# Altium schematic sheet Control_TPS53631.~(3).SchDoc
size 431 x 279 mm; Date: Not shown in title block; ApprovedBy: Not shown in title block; CheckedBy: Not shown in title block; Author: Not shown in title block; CompanyName: Not shown in title block; Engineer: Not shown in title block; Organization: Not shown in title block; Address1: Not shown in title block; Address2: Not shown in title block; Address3: Not shown in title block; Address4: Not shown in title block; DocumentNumber: 3; Revision: Use project parameter SCH_Rev; SheetNumber: 3; SheetTotal: 5; PageSetup: Record=PageOptions|CenterHorizontal=True|CenterVertical=True|PrintScale=1.00|XCorrection=1.00|YCorrection=1.00|PrintKind=0|BorderSize=5000000|LeftOffset=0|BottomOffset=0|Orientation=2|PaperLength=1000|PaperWidth=1000|Scale=100|PaperSource=15|PrintQuality=600|MediaType=1|DitherType=10|PaperKind=Letter|PrintScaleMode=1
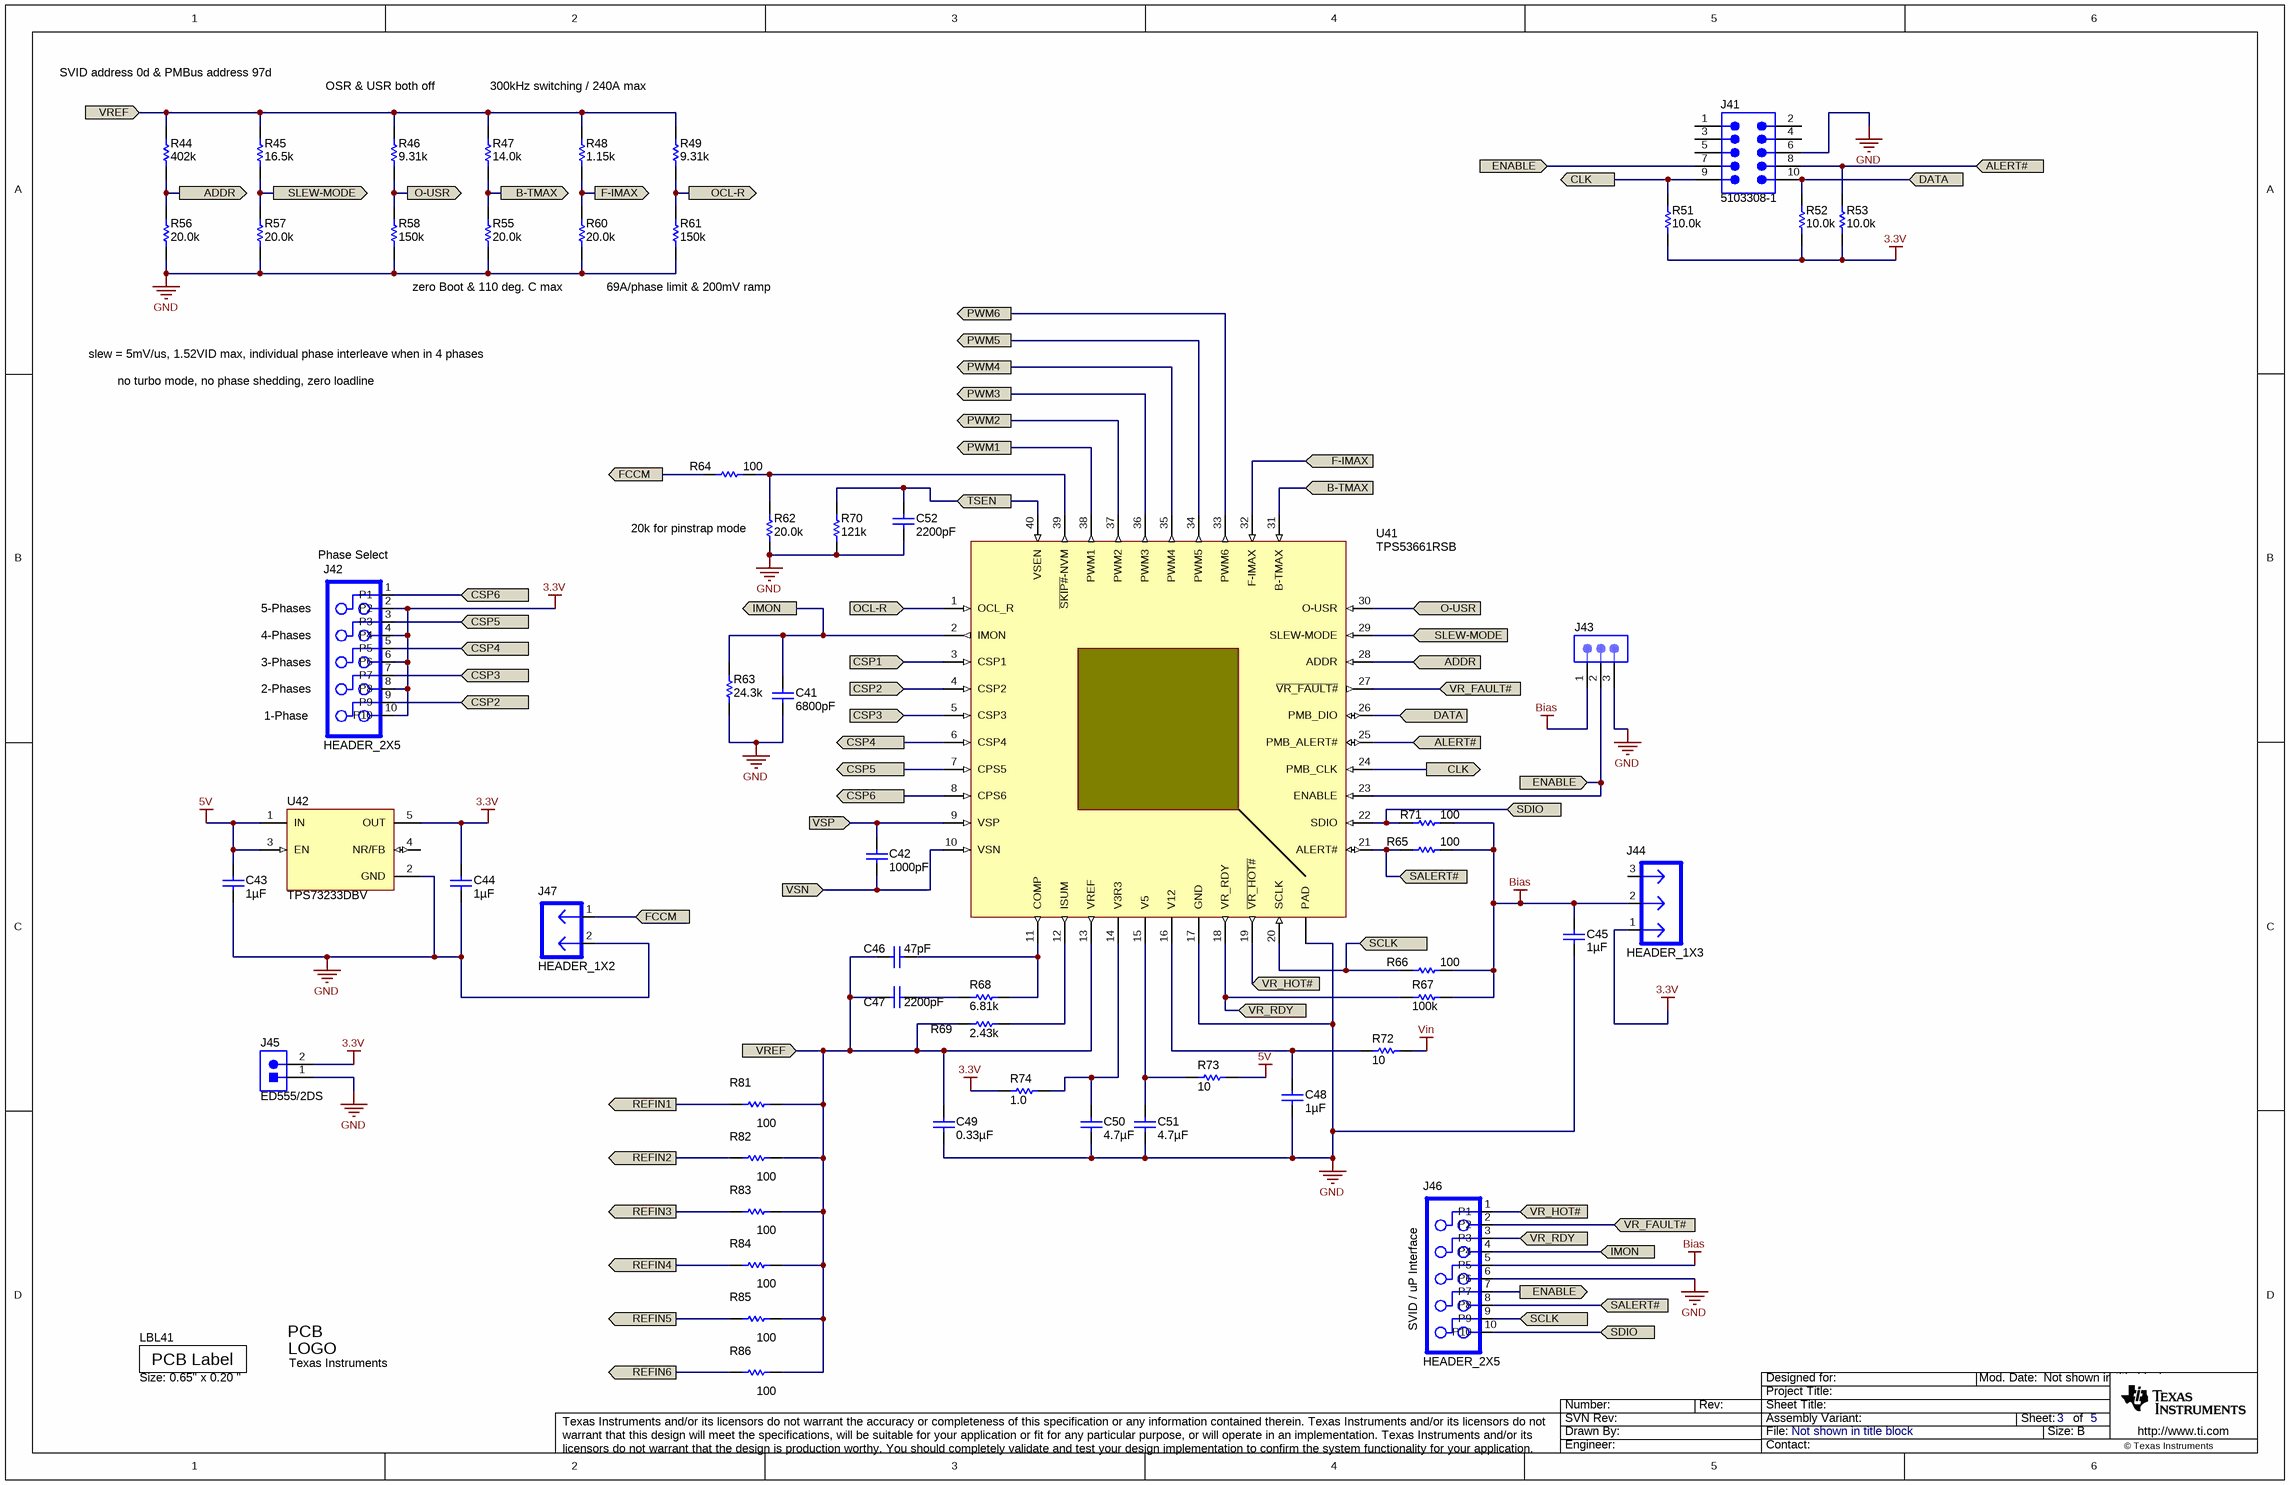
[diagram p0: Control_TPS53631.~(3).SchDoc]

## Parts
C41  ValueDisplayed: 6800pF  [0603]  (hidden comment: 06031C682KAT2A)
C42  ValueDisplayed: 1000pF  [0402]  (hidden comment: C1005X7R1H102K)
C43  ValueDisplayed: 1µF  [0603]  (hidden comment: C1608X5R1E105K080AC)
C44  ValueDisplayed: 1µF  [0603]  (hidden comment: C1608X5R1E105K080AC)
C45  ValueDisplayed: 1µF  [0603]  (hidden comment: C1608X5R1E105K080AC)
C46  ValueDisplayed: 47pF  [0402]  (hidden comment: GRM1555C1H470JA01D)
C47  ValueDisplayed: 2200pF  [0603]  (hidden comment: GRM188R71H222KA01D)
C48  ValueDisplayed: 1µF  [0603]  (hidden comment: C1608X5R1E105K080AC)
C49  ValueDisplayed: 0.33µF  [0402]  (hidden comment: GRM155R60J334KE01D)
C50  ValueDisplayed: 4.7µF  [0402]  (hidden comment: GRM155R61A475M)
C51  ValueDisplayed: 4.7µF  [0402]  (hidden comment: GRM155R61A475M)
C52  ValueDisplayed: 2200pF  [0402]  (hidden comment: C1005X7R1H222K)
J41  5103308-1  [CONN_5103308-1]
J42  HEADER_2X5  [HEADER_2X5]
J43  PBC03SAAN  [PBC03SAAN]  (value not drawn)
J44  HEADER_1X3  [HDR100_1X3]
J45  ED555/2DS  [TERM_BLK_ED555-2DS]
J46  HEADER_2X5  [HEADER_2X5]
J47  HEADER_1X2  [HDR100_1X2]
LBL41  Size: 0.65" x 0.20 "  [Label_650x200]
Logo41  Texas Instruments  [TI_Stacked_Overlay_Medium]  (no BOM)
R44  value 402k  [0402]  (hidden comment: CRCW0402402KFKED)
R45  value 16.5k  [0402]  (hidden comment: CRCW040216K5FKED)
R46  value 9.31k  [0402]  (hidden comment: CRCW04029K31FKED)
R47  value 14.0k  [0402]  (hidden comment: CRCW040214K0FKED)
R48  value 1.15k  [0402]  (hidden comment: CRCW04021K15FKED)
R49  value 9.31k  [0402]  (hidden comment: CRCW04029K31FKED)
R51  value 10.0k  [0402]  (hidden comment: CRCW040210K0FKED)
R52  value 10.0k  [0402]  (hidden comment: CRCW040210K0FKED)
R53  value 10.0k  [0402]  (hidden comment: CRCW040210K0FKED)
R55  value 20.0k  [0402]  (hidden comment: CRCW040220K0FKED)
R56  value 20.0k  [0402]  (hidden comment: CRCW040220K0FKED)
R57  value 20.0k  [0402]  (hidden comment: CRCW040220K0FKED)
R58  value 150k  [0402]  (hidden comment: CRCW0402150KFKED)
R60  value 20.0k  [0402]  (hidden comment: CRCW040220K0FKED)
R61  value 150k  [0402]  (hidden comment: CRCW0402150KFKED)
R62  value 20.0k  [0402]  (hidden comment: CRCW040220K0FKED)
R63  value 24.3k  [0402]  (hidden comment: CRCW040224K3FKED)
R64  value 100  [0402]  (hidden comment: CRCW0402100RJNED)
R65  value 100  [0402]  (hidden comment: CRCW0402100RJNED)
R66  value 100  [0402]  (hidden comment: CRCW0402100RJNED)
R67  value 100k  [0402]  (hidden comment: CRCW0402100KFKED)
R68  value 6.81k  [0402]  (hidden comment: CRCW04026K81FKED)
R69  value 2.43k  [0402]  (hidden comment: CRCW04022K43FKED)
R70  value 121k  [0402]  (hidden comment: CRCW0402121KFKED)
R71  value 100  [0402]  (hidden comment: CRCW0402100RJNED)
R72  value 10  [0402]  (hidden comment: CRCW040210R0JNED)
R73  value 10  [0402]  (hidden comment: CRCW040210R0JNED)
R74  value 1.0  [0402]  (hidden comment: CRCW04021R00JNED)
R81  value 100  [0402]  (hidden comment: CRCW0402100RJNED)
R82  value 100  [0402]  (hidden comment: CRCW0402100RJNED)
R83  value 100  [0402]  (hidden comment: CRCW0402100RJNED)
R84  value 100  [0402]  (hidden comment: CRCW0402100RJNED)
R85  value 100  [0402]  (hidden comment: CRCW0402100RJNED)
R86  value 100  [0402]  (hidden comment: CRCW0402100RJNED)
U41  TPS53661RSB  [RSB0040E]
U42  TPS73233DBV  [DBV0005A_N]

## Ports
ADDR (in), ADDR (out), ALERT#, ALERT# (in), B-TMAX (in), B-TMAX (out), CLK, CSP1 (in), CSP2, CSP2 (in), CSP3, CSP3 (in), CSP4, CSP5, CSP6, DATA, DATA (in), ENABLE, F-IMAX (in), F-IMAX (out), FCCM, IMON, O-USR (in), O-USR (out), OCL-R (in), OCL-R (out), PWM1 (out), PWM2 (out), PWM3 (out), PWM4 (out), PWM5 (out), PWM6 (out), REFIN1 (out), REFIN2 (out), REFIN3 (out), REFIN4 (out), REFIN5 (out), REFIN6 (out), SALERT#, SCLK, SDIO, SLEW-MODE (in), SLEW-MODE (out), TSEN, VR_FAULT#, VR_HOT#, VR_RDY, VREF, VSN (in), VSP (in)

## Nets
3.3V: C44.2 J42.2(P2) J42.4(P4) J42.6(P6) J42.8(P8) J42.10(P10) J44.1 J45.2 R51.2 R52.2 R53.2 R74.1 U42.5(OUT)
5V: C43.2 R73.2 U42.1(IN) U42.3(EN)
Bias: C45.1 J43.1 J44.2 J46.5(P5) R65.1 R66.1 R67.1 R71.1
GND: C41.2 C43.1 C44.1 C45.2 C48.2 C49.2 C50.2 C51.2 C52.2 J41.6 J43.3 J45.1 J46.6(P6) J47.2 R55.1 R56.1 R57.1 R58.1 R60.1 R61.1 R62.1 R63.1 R70.1 U41.17(GND) U41.41(PAD) U42.2(GND)
Vin: R72.2
ADDR: R44.1 R56.2 U41.28(ADDR) ; port ADDR
ALERT#: J41.8 R53.1 U41.25(PMB_ALERT#) ; port ALERT#
B-TMAX: R47.1 R55.2 U41.31(B-TMAX) ; port B-TMAX
CLK: J41.9 R51.1 U41.24(PMB_CLK) ; port CLK
CSP1: U41.3(CSP1) ; port CSP1
CSP2: J42.9(P9) U41.4(CSP2) ; port CSP2
CSP3: J42.7(P7) U41.5(CSP3) ; port CSP3
CSP4: J42.5(P5) U41.6(CSP4) ; port CSP4
CSP5: J42.3(P3) U41.7(CPS5) ; port CSP5
CSP6: J42.1(P1) U41.8(CPS6) ; port CSP6
DATA: J41.10 R52.1 U41.26(PMB_DIO) ; port DATA
ENABLE: J41.7 J43.2 J46.7(P7) U41.23(ENABLE) ; port ENABLE
F-IMAX: R48.1 R60.2 U41.32(F-IMAX) ; port F-IMAX
FCCM: J47.1 R64.2 ; port FCCM
IMON: C41.1 J46.4(P4) R63.2 U41.2(IMON) ; port IMON
O-USR: R46.1 R58.2 U41.30(O-USR) ; port O-USR
OCL-R: R49.1 R61.2 U41.1(OCL_R) ; port OCL-R
PWM1: U41.38(PWM1) ; port PWM1
PWM2: U41.37(PWM2) ; port PWM2
PWM3: U41.36(PWM3) ; port PWM3
PWM4: U41.35(PWM4) ; port PWM4
PWM5: U41.34(PWM5) ; port PWM5
PWM6: U41.33(PWM6) ; port PWM6
REFIN1: R81.2 ; port REFIN1
REFIN2: R82.2 ; port REFIN2
REFIN3: R83.2 ; port REFIN3
REFIN4: R84.2 ; port REFIN4
REFIN5: R85.2 ; port REFIN5
REFIN6: R86.2 ; port REFIN6
SALERT#: J46.8(P8) R65.2 U41.21(ALERT#) ; port SALERT#
SCLK: J46.9(P9) R66.2 U41.20(SCLK) ; port SCLK
SDIO: J46.10(P10) R71.2 U41.22(SDIO) ; port SDIO
SLEW-MODE: R45.1 R57.2 U41.29(SLEW-MODE) ; port SLEW-MODE
TSEN: C52.1 R70.2 U41.40(VSEN) ; port TSEN
VR_FAULT#: J46.2(P2) U41.27(~{VR_FAULT#}) ; port VR_FAULT#
VR_HOT#: J46.1(P1) U41.19(~{VR_HOT#}) ; port VR_HOT#
VR_RDY: J46.3(P3) R67.2 U41.18(VR_RDY) ; port VR_RDY
VREF: C46.1 C47.1 C49.1 R44.2 R45.2 R46.2 R47.2 R48.2 R49.2 R69.1 R81.1 R82.1 R83.1 R84.1 R85.1 R86.1 U41.13(VREF) ; port VREF
VSN: C42.2 U41.10(VSN) ; port VSN
VSP: C42.1 U41.9(VSP) ; port VSP
NetC46_2: C46.2 R68.1 U41.11(COMP)
NetC47_2: C47.2 R68.2
NetC48_1: C48.1 R72.1 U41.16(V12)
NetC50_1: C50.1 R74.2 U41.14(V3R3)
NetC51_1: C51.1 R73.1 U41.15(V5)
NetR62_2: R62.2 R64.1 U41.39(~{SKIP#}-NVM)
NetR69_2: R69.2 U41.12(ISUM)

Not connected (* = marked no-connect by the designer): J41 1 2 3 4 5; J44 3; U42 4(NR/FB)

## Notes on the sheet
- SVID address 0d & PMBus address 97d
- OSR & USR both off
- 300kHz switching / 240A max
- zero Boot & 110 deg. C max
- 69A/phase limit & 200mV ramp
- slew = 5mV/us, 1.52VID max, individual phase interleave when in 4 phases
- no turbo mode, no phase shedding, zero loadline
- (near J42) Phase Select
- (near R62) 20k for pinstrap mode
- 4-Phases
- 5-Phases
- 3-Phases
- 2-Phases
- 1-Phase
- SVID / uP Interface

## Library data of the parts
C41 = 06031C682KAT2A: CAP, CERM, 6800pF, 100V, +/-10%, X7R, 0603; Manufacturer: AVX; Polarized: N; CompType: Capacitor; U/M: EA; Cap_F: 0.0000000068; Tolerance_%: 10; ESR_Ohm: 0.115; Value1: 0.115 ohm; VDC_V: 100; TaMin_C: -55; TaMax_C: 125
C42 = C1005X7R1H102K: CAP, CERM, 1000pF, 50V, +/-10%, X7R, 0402; Manufacturer: TDK; Polarized: N; CompType: Capacitor; U/M: EA; Cap_F: 0.000000001; Tolerance_%: 10; ESR_Ohm: 0.2381; Value1: 0.2381 ohm; VDC_V: 50; TaMin_C: -55; TaMax_C: 125
C43-C45 C48 = C1608X5R1E105K080AC: CAP, CERM, 1uF, 25V, +/-10%, X5R, 0603; Manufacturer: TDK; Polarized: N; CompType: Capacitor; U/M: EA; Cap_F: 0.000001; Tolerance_%: 10; Value1: Unknown; VDC_V: 25; TaMin_C: -55; TaMax_C: 85
C46 = GRM1555C1H470JA01D: CAP, CERM, 47pF, 50V, +/-5%, C0G/NP0, 0402; Manufacturer: MuRata; Polarized: N; CompType: Capacitor; U/M: EA; Cap_F: 0.000000000047; Tolerance_%: 5; Value1: Unknown; VDC_V: 50; TaMin_C: -55; TaMax_C: 125
C47 = GRM188R71H222KA01D: CAP, CERM, 2200pF, 50V, +/-10%, X7R, 0603; Manufacturer: MuRata; Polarized: N; CompType: Capacitor; U/M: EA; Cap_F: 0.0000000022; Tolerance_%: 10; Value1: Unknown; VDC_V: 50; TaMin_C: -55; TaMax_C: 125
C49 = GRM155R60J334KE01D: CAP, CERM, 0.33uF, 6.3V, +/-10%, X5R, 0402; Manufacturer: MuRata; Polarized: N; CompType: Capacitor; U/M: EA; Cap_F: 0.00000033; Tolerance_%: 10; Value1: Unknown; VDC_V: 6.3; TaMin_C: -55; TaMax_C: 85
C50 C51 = GRM155R61A475M: CAP, CERM, 4.7uF, 10V, +/-20%, X5R, 0402; Manufacturer: MuRata; Polarized: N; CompType: Capacitor; U/M: EA; Cap_F: 0.0000047; Tolerance_%: 20; Value1: Unknown; VDC_V: 10; TaMin_C: -55; TaMax_C: 85
C52 = C1005X7R1H222K: CAP, CERM, 2200pF, 50V, +/-10%, X7R, 0402; Manufacturer: TDK; Polarized: N; CompType: Capacitor; U/M: EA; Cap_F: 0.0000000022; Tolerance_%: 10; ESR_Ohm: 0.1433; Value1: 0.1433 ohm; VDC_V: 50; TaMin_C: -55; TaMax_C: 125
J41 = 5103308-1: Header (shrouded), 100mil, 5x2, Gold, TH; Manufacturer: TE Connectivity; SymbolCreator: a0412235; CompType: Connector; U/M: EA
J42 J46 = HEADER_2X5: Header, Male 2x5-pin, 100mil spacing; Manufacturer: Sullins; PartNumber: PEC05DAAN; area: 100000; Value: PEC05DAAN
J43 = PBC03SAAN: Header, TH, 100mil, 1x3, Gold plated, 230 mil above insulator; Manufacturer: Sullins Connector Solutions; U/M: EA
J44 = HEADER_1X3: Header, Male 3-pin, 100mil spacing,; Manufacturer: Sullins; PartNumber: PEC03SAAN; area: 30000; Value: PEC03SAAN
J45 = ED555/2DS: Terminal Block, 6A, 3.5mm Pitch, 2-Pos, TH; Manufacturer: On-Shore Technology; SymbolCreator: a0412235; CompType: Connector; U/M: EA
J47 = HEADER_1X2: Header, Male 2-pin, 100mil spacing,; Manufacturer: Sullins; PartNumber: PEC02SAAN; area: 20000; Value: PEC02SAAN
LBL41 = THT-14-423-10: Thermal Transfer Printable Labels, 0.650" W x 0.200" H - 10,000 per roll; Manufacturer: Brady; SymbolCreator: a0412235; CompType: Label
Logo41 = TI_Logo: Texas Instrument Corporate Signature; SymbolCreator: a0412235
R44 = CRCW0402402KFKED: RES, 402k ohm, 1%, 0.063W, 0402; Manufacturer: Vishay-Dale; CompType: Resistor; Res_ohm: 402000; Tolerance_%: 1; Power_W: 0.063; VDC_V: 50; TempCo: 100 ppm/C; EIA_Code: E96; U/M: EA
R45 = CRCW040216K5FKED: RES, 16.5k ohm, 1%, 0.063W, 0402; Manufacturer: Vishay-Dale; CompType: Resistor; Res_ohm: 16500; Value_Code: 16k5; Tolerance_%: 1; Power_W: 0.063; VDC_V: 50; TempCo: 100 ppm/C; EIA_Code: E96; U/M: EA
R46 R49 = CRCW04029K31FKED: RES, 9.31k ohm, 1%, 0.063W, 0402; Manufacturer: Vishay-Dale; CompType: Resistor; Res_ohm: 9310; Value_Code: 9k31; Tolerance_%: 1; Power_W: 0.063; VDC_V: 50; TempCo: 100 ppm/C; EIA_Code: E96; U/M: EA
R47 = CRCW040214K0FKED: RES, 14.0k ohm, 1%, 0.063W, 0402; Manufacturer: Vishay-Dale; CompType: Resistor; Res_ohm: 14000; Value_Code: 14k0; Tolerance_%: 1; Power_W: 0.063; VDC_V: 50; TempCo: 100 ppm/C; EIA_Code: E96; U/M: EA
R48 = CRCW04021K15FKED: RES, 1.15k ohm, 1%, 0.063W, 0402; Manufacturer: Vishay-Dale; CompType: Resistor; Res_ohm: 1150; Value_Code: 1k15; Tolerance_%: 1; Power_W: 0.063; VDC_V: 50; TempCo: 100 ppm/C; EIA_Code: E96; U/M: EA
R51-R53 = CRCW040210K0FKED: RES, 10.0k ohm, 1%, 0.063W, 0402; Manufacturer: Vishay-Dale; CompType: Resistor; Res_ohm: 10000; Value_Code: 10k0; Tolerance_%: 1; Power_W: 0.063; VDC_V: 50; TempCo: 100 ppm/C; EIA_Code: E96; U/M: EA
R55-R57 R60 R62 = CRCW040220K0FKED: RES, 20.0k ohm, 1%, 0.063W, 0402; Manufacturer: Vishay-Dale; CompType: Resistor; Res_ohm: 20000; Value_Code: 20k0; Tolerance_%: 1; Power_W: 0.063; VDC_V: 50; TempCo: 100 ppm/C; EIA_Code: E96; U/M: EA
R58 R61 = CRCW0402150KFKED: RES, 150k ohm, 1%, 0.063W, 0402; Manufacturer: Vishay-Dale; CompType: Resistor; Res_ohm: 150000; Tolerance_%: 1; Power_W: 0.063; VDC_V: 50; TempCo: 100 ppm/C; EIA_Code: E96; U/M: EA
R63 = CRCW040224K3FKED: RES, 24.3k ohm, 1%, 0.063W, 0402; Manufacturer: Vishay-Dale; CompType: Resistor; Res_ohm: 24300; Value_Code: 24k3; Tolerance_%: 1; Power_W: 0.063; VDC_V: 50; TempCo: 100 ppm/C; EIA_Code: E96; U/M: EA
R64-R66 R71 R81-R86 = CRCW0402100RJNED: RES, 100 ohm, 5%, 0.063W, 0402; Manufacturer: Vishay-Dale; CompType: Resistor; Value_Code: 100R; Tolerance_%: 5; Power_W: 0.063; VDC_V: 50; TempCo: 200 ppm/C; EIA_Code: E24; U/M: EA
R67 = CRCW0402100KFKED: RES, 100k ohm, 1%, 0.063W, 0402; Manufacturer: Vishay-Dale; CompType: Resistor; Res_ohm: 100000; Tolerance_%: 1; Power_W: 0.063; VDC_V: 50; TempCo: 100 ppm/C; EIA_Code: E96; U/M: EA
R68 = CRCW04026K81FKED: RES, 6.81k ohm, 1%, 0.063W, 0402; Manufacturer: Vishay-Dale; CompType: Resistor; Res_ohm: 6810; Value_Code: 6k81; Tolerance_%: 1; Power_W: 0.063; VDC_V: 50; TempCo: 100 ppm/C; EIA_Code: E96; U/M: EA
R69 = CRCW04022K43FKED: RES, 2.43k ohm, 1%, 0.063W, 0402; Manufacturer: Vishay-Dale; CompType: Resistor; Res_ohm: 2430; Value_Code: 2k43; Tolerance_%: 1; Power_W: 0.063; VDC_V: 50; TempCo: 100 ppm/C; EIA_Code: E96; U/M: EA
R70 = CRCW0402121KFKED: RES, 121k ohm, 1%, 0.063W, 0402; Manufacturer: Vishay-Dale; CompType: Resistor; Res_ohm: 121000; Tolerance_%: 1; Power_W: 0.063; VDC_V: 50; TempCo: 100 ppm/C; EIA_Code: E96; U/M: EA
R72 R73 = CRCW040210R0JNED: RES, 10 ohm, 5%, 0.063W, 0402; Manufacturer: Vishay-Dale; CompType: Resistor; Value_Code: 10R0; Tolerance_%: 5; Power_W: 0.063; VDC_V: 50; TempCo: 200 ppm/C; EIA_Code: E24; U/M: EA
R74 = CRCW04021R00JNED: RES, 1.0 ohm, 5%, 0.063W, 0402; Manufacturer: Vishay-Dale; CompType: Resistor; Res_ohm: 1; Value_Code: 1R00; Tolerance_%: 5; Power_W: 0.063; VDC_V: 50; TempCo: 200 ppm/C; EIA_Code: E24; U/M: EA
U41 = TPS53661RSB: 6-Phase, D-CAP+ Step-Down VR12.x Server CPU VCORE and DDR Memory Controller with PMBus Interface, RSB0040E; Alternate Manufacturer: None; Manufacturer: Texas Instruments; SymbolCreator: a0799628; CompType: IC; U/M: EA
U42 = TPS73233DBV: Cap-Free, NMOS, 250mA Low Dropout Regulator with Reverse Current Protection, DBV0005A; Alternate Manufacturer: None; Manufacturer: Texas Instruments; SymbolCreator: a0411947; CompType: IC; U/M: EA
